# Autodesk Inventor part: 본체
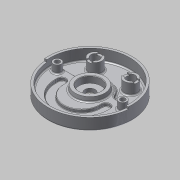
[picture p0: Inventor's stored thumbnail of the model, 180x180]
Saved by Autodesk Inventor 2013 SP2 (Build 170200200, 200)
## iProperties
Created: 2015-04
Part Number: 본체
Material: 알루미늄 6061
Document SubType Name: Modeling
Designer: dgall
Density: 2.71 g/cm^3
Mass: 1044.55 g
Surface Area: 1020.02 cm^2
Volume: 385.443 cm^3
Author: dgall
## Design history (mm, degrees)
sketch "스케치1"
  geometry: C1 r 95 at (0, 0); 1 further point
  constraints: 1 centre point, 1 coincident
  dimensions: "d0" = 190 diameter of C1
extrude "돌출1" new body sketch "스케치1" distance "d2" = 32; taper "d3" = 0 deg
sketch "스케치2"
  geometry: L1 (-76.916, 12)-(-47.117, 12); L2 (-40.249, 12)-(40.249, 12); L3 (47.117, 12)-(76.916, 12); L4 (-73.457, 52)-(73.457, 52); L5 (0, 42)-(0, 0); L6 (-46, 65.748)-(-46, 38.252); L7 (-34, 65.748)-(-34, 38.252); L8 (26.252, 58)-(53.748, 58); L9 (53.748, 46)-(26.252, 46); C1 r 95 at (0, 0) reference; C2 r 10 at (-40, 52); C3 r 10 at (40, 52); A1 r 90 centre (0, 0) between (86.53, 24.75) and (-86.53, 24.75); A2 r 10 centre (-76.916, 22) between (-86.53, 24.75) and (-76.916, 12); A3 r 10 centre (-47.117, 22) between (-47.117, 12) and (-38.056, 17.769); A4 r 10 centre (47.117, 22) between (38.056, 17.769) and (47.117, 12); A5 r 10 centre (76.916, 22) between (76.916, 12) and (86.53, 24.75); A6 r 42 centre (0, 0) between (-40.249, 12) and (40.249, 12); A7 r 42 centre (0, 0) between (38.056, 17.769) and (-38.056, 17.769); A8 r 15 centre (-40, 52) between (-46, 65.748) and (-46, 38.252); A9 r 15 centre (40, 52) between (26.252, 58) and (53.748, 58)
  constraints: 25 point on circle, 18 end point, 14 tangent, 11 centre point, 6 parallel, 4 coincident, 3 horizontal, 2 perpendicular, 2 symmetric about line, 1 point on line, 2 other
  dimensions: "d6" = 180 diameter of A1; "d8" = 20 diameter of A2; "d9" = 20 diameter of A3; "d10" = 20 diameter of A4; "d11" = 20 diameter of A5; "d12" = 22 vertical distance of C1.centre A3.centre; "d13" = 42 radius of A7; "d15" = 29.79866 distance of A3.centre A2.centre; "d16" = 29.79866 distance of A5.centre A4.centre; "d17" = 52 distance from line of C1.centre L4; "d18" = 40 horizontal distance of C1.centre A8.centre; "d19" = 30 diameter of A8; "d20" = 20 diameter of C2; "d21" = 12 distance between parallel lines of L7 L6; "d23" = 12 distance between parallel lines of L9 L8
extrude "돌출2" cut sketch "스케치2" distance "d24" = 25; taper "d25" = 0 deg
extrude "돌출3" cut sketch "스케치2" stored distance "d26" = 25; taper "d27" = 0 deg
extrude "돌출4" cut sketch "스케치2" distance "d28" = 3; taper "d29" = 0 deg
sketch "스케치3"
  geometry: L1 (-47.117, 12)-(-76.916, 12) reference; L2 (76.916, 12)-(47.117, 12) reference; C1 r 95 at (0, 0) reference; C2 r 90 at (0, 0); A1 r 10 centre (-47.117, 22) between (-47.117, 12) and (-38.056, 17.769) reference; A2 r 10 centre (-76.916, 22) between (-86.53, 24.75) and (-76.916, 12) reference; A3 r 90 centre (0, 0) between (86.53, 24.75) and (-86.53, 24.75) reference; A4 r 10 centre (76.916, 22) between (76.916, 12) and (86.53, 24.75) reference; A5 r 10 centre (47.117, 22) between (38.056, 17.769) and (47.117, 12) reference; A6 r 42 centre (0, 0) between (38.056, 17.769) and (-38.056, 17.769) reference
  constraints: 1 centre point, 1 coincident
  dimensions: "d30" = 180 diameter of C2
extrude "돌출5" cut sketch "스케치3" distance "d34" = 18; taper "d35" = 0 deg
sketch "스케치4"
  geometry: C1 r 35 at (0, 0); C2 r 25 at (0, 0); A1 r 42 centre (0, 0) between (38.056, 17.769) and (-38.056, 17.769) reference
  constraints: 2 centre point, 2 coincident
  dimensions: "d36" = 70 diameter of C1; "d38" = 50 diameter of C2
extrude "돌출6" join sketch "스케치4" distance "d39" = 10; taper "d40" = 0 deg
sketch "스케치5"
  geometry: C1 r 25 at (0, 0) reference; C2 r 11.5 at (0, 0)
  constraints: 1 centre point, 1 coincident
  dimensions: "d41" = 23 diameter of C2
extrude "돌출7" cut sketch "스케치5" stored distance "d43" = 10; taper "d44" = 0 deg
sketch "스케치6"
  geometry: L1 (-76.916, 12)-(-47.117, 12) reference; L2 (-87.972, -19)-(87.972, -19); L3 (-59, -19)-(59, -19); L4 (-59, -19)-(-59, -14); L5 (-41, -19)-(-41, -14); L6 (-59, -14)-(-41, -14); L7 (0, -19)-(0, -60); L8 (59, -19)-(59, -14); L9 (41, -19)-(41, -14); C1 r 35 at (0, 0) reference; C2 r 42 at (0, 0); A1 r 90 centre (0, 0) between (-86.53, 24.75) and (86.53, 24.75) reference; A2 r 41 centre (0, -19) between (-41, -19) and (41, -19); A3 r 59 centre (0, -19) between (-59, -19) and (59, -19); A4 r 9 centre (-50, -14) between (-41, -14) and (-59, -14); A5 r 9 centre (50, -14) between (59, -14) and (41, -14)
  constraints: 16 end point, 11 point on circle, 5 centre point, 4 point on line, 3 symmetric about line, 2 coincident, 2 midpoint, 2 parallel, 2 perpendicular, 2 tangent, 1 other
  dimensions: "d45" = 19 distance from line of L2 A1.centre; "d50" = 84 diameter of C2; "d52" = 59 radius of A3; "d53" = 41 radius of A2; "d54" = 5 vertical distance of L7.start A4.centre
extrude "돌출8" cut sketch "스케치6" distance "d55" = 7; taper "d56" = 0 deg
sketch "스케치7"
  geometry: C1 r 9 at (-74, 0); C2 r 5.5 at (-74, 0); A1 r 90 centre (0, 0) between (-86.53, 24.75) and (86.53, 24.75) reference
  constraints: 2 centre point, 1 coincident, 1 horizontal alignment
  dimensions: "d57" = 18 diameter of C1; "d59" = 11 diameter of C2; "d60" = 74 distance of A1.centre C2.centre
extrude "돌출9" join sketch "스케치7" distance "d61" = 18; taper "d62" = 0 deg
extrude "돌출10" cut sketch "스케치7" stored distance "d63" = 13; taper "d64" = 0 deg
sketch "스케치9"
  geometry: C1 r 5.5 at (-74, 0) reference; C2 r 5.5 at (74, 0) reference; C3 r 9 at (-74, 0); C4 r 9 at (74, 0)
  constraints: 2 centre point, 2 coincident, 1 equal radius
  dimensions: "d65" = 18 diameter of C3
extrude "돌출11" cut sketch "스케치9" distance "d67" = 11; taper "d68" = 0 deg
sketch "스케치10"
  geometry: L1 (0, 0)-(-94.638, -8.28); L2 (0, 0)-(94.638, -8.28); L3 (-95, 0)-(95, 0); L4 (-94.638, -8.28)-(-89.658, -7.844); L5 (89.658, -7.844)-(94.638, -8.28); A1 r 95 centre (0, 0) between (-94.638, -8.28) and (94.638, -8.28) reference; A2 r 95 centre (0, 0) between (-94.638, -8.28) and (94.638, -8.28); A3 r 90 centre (0, 0) between (-89.658, -7.844) and (89.658, -7.844)
  constraints: 10 end point, 8 point on circle, 2 centre point, 2 coincident, 2 collinear, 1 horizontal, 1 point on line, 2 other
  dimensions: "d69" = 5 deg angle of L2 L3; "d70" = 5 deg angle of L1 L3
extrude "돌출12" cut sketch "스케치10" distance "d71" = 5; taper "d72" = 0 deg
sketch "스케치11"
  geometry: L1 (-19, 14)-(-60, 14) reference; L2 (-35, 14)-(-35, 24) reference; L3 (-35, 14)-(-33.237, 24); L4 (-35, 30.674)-(-35.032, 30.674); L5 (-35.027, 24)-(-35, 14); L6 (35, 24)-(-35, 24) reference; L7 (-35.027, 24)-(-33.237, 24); L8 (0, 0)-(0, 44.642)
  constraints: 10 end point, 3 point on line, 1 collinear, 1 horizontal, 1 perpendicular
  dimensions: "d73" = 100 deg angle of L1 L3
revolve "회전1" sketch "스케치11" stored, may be unused: angle "d74" = 90 deg
sketch "스케치12"
  geometry: C1 r 25 at (0, 0) reference
extrude "돌출13" cut sketch "스케치12" distance "d75" = 15; taper "d76" = 0 deg
sketch "스케치13"
  geometry: L1 (-36.062, -36.062)-(-50.912, -50.912); L2 (36.062, -36.062)-(50.912, -50.912); L3 (0, 0)-(0, -72); C1 r 95 at (0, 0) reference; A1 r 72 centre (0, 0) between (-50.912, -50.912) and (50.912, -50.912); A2 r 51 centre (0, 0) between (-36.062, -36.062) and (36.062, -36.062); 1 further point
  constraints: 6 end point, 5 point on circle, 2 centre point, 2 coincident, 1 vertical
  dimensions: "d83" = 144 diameter of A1; "d85" = 102 diameter of A2; "d86" = 90 deg angle of L2 L1; "d87" = 45 deg angle of L1 L3
extrude "돌출14" join sketch "스케치13" distance "d88" = 5; taper "d89" = 0 deg
sketch "스케치14"
  geometry: L1 (-36.062, -36.062)-(-50.912, -50.912) reference; L2 (50.912, -50.912)-(36.062, -36.062) reference; A1 r 72 centre (0, 0) between (-50.912, -50.912) and (50.912, -50.912) reference; A2 r 51 centre (0, 0) between (-36.062, -36.062) and (36.062, -36.062) reference
fillet "모깎기1" dims "d92" = 5
fillet "모깎기2" dims "d93" = 5
fillet "모깎기3" dims "d94" = 3
chamfer "모따기1" distance "d95" = 1; stored, may be unused: second distance "d96" = 2, angle "d97" = 45 deg
fillet "모깎기4" dims "d98" = 1
fillet "모깎기5" dims "d99" = 3
node "솔리드1"
mirror "대칭1"
other parameters: "d4" = 84, "d7" = 12, "d46" = 118, "d47" = 82, "d51" = 5
